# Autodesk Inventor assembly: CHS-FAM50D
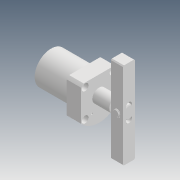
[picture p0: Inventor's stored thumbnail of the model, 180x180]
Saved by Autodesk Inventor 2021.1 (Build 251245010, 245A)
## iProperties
Created: 2019-04
Part Number: CHS-FAM50D
Description: STEP AP203
Document SubType Name: Assembly
Designer: user
Title: chs-fam50d_asm.STEP
Revision Number: ÈÎºÎ
Sending System: SolidWorks 2017
Preprocessor: SwSTEP 2.0
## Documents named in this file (7)
- D:\Vault_2016\Projekty\Clamptek\Hydraulic\CHS\CHS-50\Inventor\CHS-FAM50D\CHS-FAM50D.iam
- D:\Vault_2016\Projekty\Clamptek\Hydraulic\CHS\CHS-50\Inventor\CHS-FAM50D\CHS-FAM50BT_1.ipt
- D:\Vault_2016\Projekty\Clamptek\Hydraulic\CHS\CHS-50\Inventor\CHS-FAM50D\CHS-50DHSG_2.ipt
- D:\Vault_2016\Projekty\Clamptek\Hydraulic\CHS\CHS-50\Inventor\CHS-FAM50D\M6_1.ipt
- D:\Vault_2016\Projekty\Clamptek\Hydraulic\CHS\CHS-50\Inventor\CHS-FAM50D\CHS-50DYB_3.ipt
- D:\Vault_2016\Projekty\Clamptek\Hydraulic\CHS\CHS-50\Inventor\CHS-FAM50D\ÖáÓÃµ²È¦.ipt
- D:\Vault_2016\Projekty\Clamptek\Hydraulic\CHS\CHS-50\Inventor\CHS-FAM50D\Ïú.ipt
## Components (10 placed, 10 different names)
1. CHS-FAM50BT_1_1
2. CHS-50DHSG_2_2
3. M6_1_3
4. M6_1_4
5. M6_1_5
6. M6_1_6
7. CHS-50DYB_3_7
8. ÖáÓÃµ²È¦_8
9. Ïú_9
10. ÖáÓÃµ²È¦_10
